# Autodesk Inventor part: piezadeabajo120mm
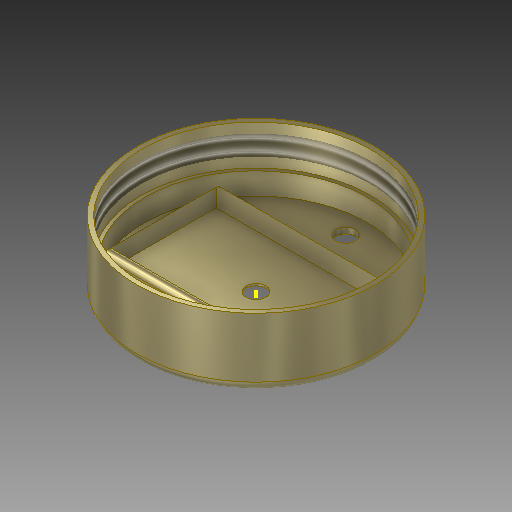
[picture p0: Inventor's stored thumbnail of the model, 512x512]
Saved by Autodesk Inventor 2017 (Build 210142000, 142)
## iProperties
Part Number: piezadeabajo120mm
Material: Oro
Document SubType Name: Modeling
Designer: Yavhee
Density: 19.3 g/cm^3
Appearance: Oro - Metal
Author: Yavhee
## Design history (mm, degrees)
sketch "Boceto1"
  geometry: 1 further point
sketch "Boceto2"
  geometry: C1 r 60 at (0, 0); 1 further point
  constraints: 1 centre point, 1 coincident
  dimensions: "d0" = 120 diameter of C1
extrude "Extrusión1" new body sketch "Boceto2" distance "d1" = 15; taper "d2" = 0 deg
feature "Vaciado1" dims "d3" = 4
sketch "Boceto3"
  geometry: L1 (-48.5, 28.5)-(48.5, 28.5); L2 (48.5, 28.5)-(48.5, -28.5); L3 (48.5, -28.5)-(-48.5, -28.5); L4 (-48.5, -28.5)-(-48.5, 28.5); L5 (-48.5, 28.5)-(48.5, -28.5); L6 (48.5, 28.5)-(-48.5, -28.5); 1 further point
  constraints: 12 end point, 2 midpoint, 2 parallel, 1 horizontal, 1 perpendicular
  dimensions: "d4" = 57 distance of L3.end L1.start; "d5" = 97 distance of L2.end L3.end
extrude "Extrusión2" join sketch "Boceto3" distance "d6" = 8; taper "d7" = 0 deg
feature "Vaciado2" dims "d8" = 2
sketch "Boceto4"
  geometry: 1 further point
sketch "Boceto5"
  geometry: 4 further points
  constraints: 1 coincident
hole "Agujero1" sketch "Boceto5" at (0, 45), (0, 0), (0, -45) diameter "d9" = 10; stored, may be unused: countersink angle "d13" = 90 deg, drill point angle "d15" = 118 deg; dims "d10" = 6, "d11" = 20, "d12" = 1, "d14" = 8
fillet "Empalme1" dims "d16" = 5
sketch "Boceto6"
  geometry: C1 r 5 at (0, 0) reference; C2 r 60 at (0, 0); C3 r 57.697 at (0, 0); 1 further point
  constraints: 2 centre point, 2 coincident
  dimensions: "d17" = 2.30251 radial gap between concentric circles of C2 C3
extrude "Extrusión3" join sketch "Boceto6" distance "d18" = 20; taper "d19" = 0 deg
fillet "Empalme2" dims "d20" = 5
feature "Rosca1" dims "d21" = 10, "d22" = 5
node "Sólido1"
other parameters: "sa_0" = 4
